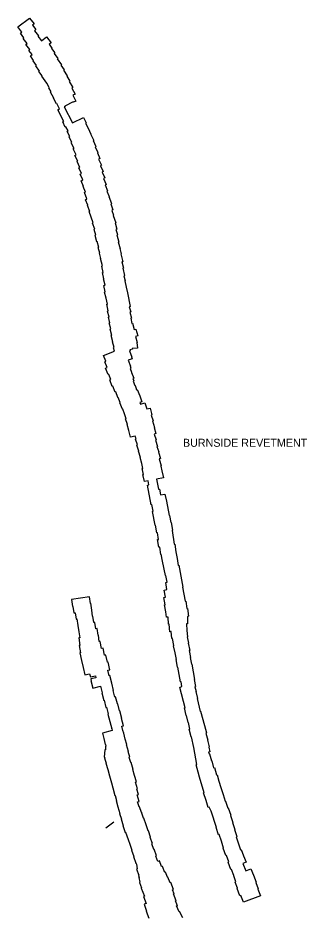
# Model space of a CAD drawing. Extents: x 2650582 to 3923188, y 277893 to 989177.
# Drawn here: x 3411893 to 3417673, y 574648 to 592623 of the extents above; entities that cross this region are included whole.
import ezdxf

# ---------------------------------------------------------------- set-up
doc = ezdxf.new("R2010")
doc.units = 0
doc.layers.add('Level 3', color=7, linetype='Continuous')

msp = doc.modelspace()

# ---------------------------------------------------------------- linework, layer by layer
at = {"layer": 'Level 3'}
msp.add_line((3413808, 576547), (3413650, 576422), dxfattribs=at)
for points in [[(3413582, 587665), (3413544, 587812), (3413550, 587813), (3413522, 587920), (3413528, 587921), (3413495, 588032), (3413508, 588035), (3413474, 588151), (3413471, 588150), (3413435, 588276), (3413448, 588280), (3413414, 588395), (3413427, 588399), (3413385, 588522), (3413399, 588527), (3413316, 588751), (3413329, 588756), (3413283, 588875), (3413289, 588878), (3413243, 588989), (3413271, 589008), (3413222, 589132), (3413242, 589140), (3413197, 589252), (3413205, 589255), (3413155, 589368), (3413192, 589384), (3413137, 589499), (3413161, 589511), (3413107, 589627), (3413127, 589637), (3413075, 589756), (3413087, 589761), (3413033, 589877), (3413054, 589887), (3413000, 590005), (3413014, 590011), (3412960, 590130), (3412972, 590136), (3412920, 590249), (3412929, 590253), (3412880, 590353), (3412894, 590365), (3412852, 590449), (3412840, 590443), (3412788, 590545), (3412807, 590555), (3412689, 590789), (3412724, 590808), (3412667, 590912), (3412664, 590910), (3412605, 591017), (3412611, 591021), (3412545, 591141), (3412559, 591150), (3412513, 591230), (3412520, 591235), (3412469, 591317), (3412372, 591461), (3412378, 591465), (3412313, 591555), (3412321, 591560), (3412248, 591666), (3412261, 591676), (3412194, 591768), (3412205, 591776), (3412142, 591866), (3412174, 591891), (3412110, 591976), (3412130, 591992), (3412053, 592095), (3412077, 592114), (3412000, 592215), (3412013, 592225), (3411943, 592317), (3411970, 592337), (3411893, 592445), (3412127, 592623)], [(3412127, 592623), (3412217, 592504), (3412185, 592478), (3412253, 592393), (3412222, 592368), (3412301, 592267), (3412292, 592261), (3412363, 592166), (3412463, 592246), (3412555, 592126), (3412518, 592097), (3412572, 592020), (3412564, 592014), (3412629, 591924), (3412616, 591914), (3412687, 591815), (3412675, 591806), (3412765, 591688), (3412751, 591677), (3412816, 591586), (3412803, 591577), (3412874, 591466), (3412868, 591462), (3412928, 591358), (3412919, 591353), (3412992, 591232), (3412970, 591218), (3413036, 591102), (3412989, 591077), (3413049, 590962), (3413005, 590938), (3413000, 590947), (3412828, 590860), (3412833, 590850), (3412820, 590844), (3412986, 590529), (3413203, 590636), (3413257, 590528), (3413245, 590522), (3413298, 590420), (3413294, 590418), (3413353, 590299), (3413350, 590297), (3413410, 590176), (3413399, 590171), (3413450, 590055), (3413437, 590049), (3413493, 589932), (3413481, 589926), (3413533, 589811), (3413506, 589798), (3413562, 589679), (3413542, 589669), (3413594, 589553), (3413574, 589543), (3413629, 589425), (3413605, 589413), (3413654, 589292), (3413634, 589284), (3413682, 589164), (3413673, 589161), (3413718, 589056), (3413708, 589051), (3413764, 588912), (3413747, 588906), (3413791, 588786), (3413768, 588776), (3413805, 588679), (3413798, 588676), (3413849, 588530), (3413834, 588525), (3413872, 588400), (3413852, 588393), (3413884, 588291), (3413869, 588286), (3413910, 588144), (3413900, 588141), (3413937, 588015), (3413933, 588013), (3413959, 587910), (3413951, 587908), (3413993, 587751), (3413971, 587746)], [(3413825, 585960), (3413804, 586030), (3413819, 586035), (3413785, 586146), (3413793, 586149), (3413758, 586273), (3413770, 586276), (3413736, 586402), (3413747, 586405), (3413720, 586525), (3413730, 586528), (3413704, 586640), (3413716, 586643), (3413684, 586762), (3413698, 586766), (3413670, 586898), (3413683, 586901), (3413655, 587023), (3413657, 587023), (3413626, 587144), (3413638, 587147), (3413607, 587276), (3413635, 587282), (3413605, 587408), (3413613, 587410), (3413583, 587534), (3413600, 587537), (3413568, 587662), (3413582, 587665)], [(3413971, 587746), (3414004, 587623), (3413987, 587619), (3414024, 587476), (3414010, 587471), (3414037, 587366), (3414030, 587365), (3414059, 587241), (3414055, 587240), (3414083, 587126), (3414086, 587127), (3414137, 586855), (3414117, 586851), (3414149, 586748), (3414128, 586742), (3414160, 586622), (3414150, 586620), (3414168, 586518), (3414185, 586522), (3414219, 586396), (3414250, 586404), (3414288, 586269), (3414242, 586256), (3414277, 586138), (3414272, 586136), (3414285, 586023), (3414177, 586014), (3414180, 586001), (3414129, 585989), (3414134, 585969), (3414125, 585967), (3414167, 585844), (3414164, 585843), (3414176, 585811), (3414098, 585781), (3414143, 585664), (3414136, 585662), (3414149, 585623), (3414134, 585617), (3414164, 585539), (3414162, 585538), (3414207, 585421), (3414193, 585416), (3414209, 585367), (3414198, 585363), (3414233, 585272), (3414234, 585272), (3414247, 585235), (3414264, 585191), (3414278, 585197), (3414328, 585066), (3414327, 585066), (3414372, 584949), (3414331, 584933), (3414342, 584899), (3414430, 584929), (3414473, 584808), (3414535, 584825), (3414573, 584688), (3414559, 584684), (3414594, 584571), (3414583, 584568), (3414626, 584436), (3414614, 584433), (3414653, 584316), (3414619, 584305)], [(3414143, 584239), (3414108, 584374), (3414111, 584375), (3414078, 584496), (3414081, 584497), (3414046, 584606), (3414055, 584609), (3414022, 584710), (3414026, 584711), (3413991, 584803), (3413984, 584800), (3413933, 584931), (3413938, 584932), (3413899, 585035), (3413893, 585033), (3413848, 585150), (3413838, 585145), (3413793, 585262), (3413778, 585256), (3413728, 585387), (3413748, 585395), (3413708, 585498), (3413696, 585493), (3413646, 585623), (3413674, 585634), (3413629, 585751), (3413649, 585759), (3413604, 585875), (3413825, 585960)], [(3414421, 583354), (3414393, 583494), (3414406, 583497), (3414379, 583615), (3414391, 583618), (3414367, 583716), (3414372, 583717), (3414335, 583835), (3414342, 583837), (3414301, 583961), (3414310, 583964), (3414270, 584081), (3414284, 584086), (3414244, 584202), (3414256, 584206), (3414237, 584264), (3414143, 584239)], [(3414619, 584305), (3414659, 584186), (3414642, 584180), (3414681, 584057), (3414673, 584054), (3414707, 583947), (3414700, 583945), (3414740, 583817), (3414719, 583811), (3414759, 583667), (3414751, 583664), (3414770, 583567), (3414773, 583568), (3414800, 583431), (3414662, 583403)], [(3415173, 579254), (3415156, 579351), (3415145, 579349), (3415119, 579499), (3415114, 579498), (3415090, 579642), (3415084, 579641), (3415057, 579796), (3415063, 579798), (3415039, 579929), (3415034, 579928), (3415005, 580073), (3415008, 580074), (3414982, 580215), (3414973, 580214), (3414956, 580354), (3414927, 580352), (3414915, 580500), (3414901, 580500), (3414898, 580642), (3414865, 580643), (3414852, 580752), (3414847, 580752), (3414822, 580889), (3414838, 580891), (3414812, 581039), (3414841, 581045), (3414815, 581186), (3414873, 581199), (3414848, 581337), (3414874, 581343), (3414849, 581476), (3414840, 581475), (3414786, 581761), (3414780, 581760), (3414756, 581900), (3414753, 581899), (3414729, 582045), (3414707, 582042), (3414682, 582193), (3414705, 582197), (3414682, 582329), (3414668, 582327), (3414642, 582484), (3414638, 582484), (3414584, 582759), (3414598, 582762), (3414571, 582893), (3414558, 582891), (3414482, 583282), (3414510, 583288), (3414495, 583369), (3414421, 583354)], [(3414662, 583403), (3414702, 583201), (3414720, 583204), (3414742, 583088), (3414831, 583104), (3414860, 582963), (3414862, 582963), (3414914, 582678), (3414922, 582679), (3414950, 582534), (3414957, 582534), (3414980, 582380), (3414974, 582379), (3415017, 582102), (3415028, 582103), (3415052, 581950), (3415051, 581949), (3415074, 581814), (3415075, 581814), (3415099, 581679), (3415111, 581681), (3415190, 581243), (3415181, 581241), (3415236, 580960), (3415247, 580962), (3415273, 580814), (3415283, 580815), (3415300, 580660), (3415285, 580659), (3415285, 580507), (3415264, 580507), (3415273, 580376), (3415269, 580376), (3415286, 580250), (3415278, 580249), (3415302, 580124), (3415299, 580124), (3415327, 579978), (3415319, 579977), (3415345, 579836), (3415339, 579835), (3415363, 579703), (3415367, 579704), (3415423, 579398), (3415416, 579397), (3415442, 579255), (3415437, 579255)], [(3413803, 579180), (3413767, 579321), (3413773, 579322), (3413733, 579474), (3413718, 579470), (3413688, 579584), (3413728, 579592), (3413696, 579745), (3413681, 579742), (3413652, 579885), (3413624, 579880), (3413596, 580022), (3413563, 580016), (3413535, 580159), (3413520, 580156), (3413501, 580286), (3413498, 580285), (3413479, 580414), (3413451, 580409), (3413431, 580538), (3413410, 580535), (3413391, 580664), (3413386, 580664), (3413368, 580781), (3413373, 580781), (3413353, 580920), (3413344, 580919), (3413325, 581048), (3412965, 580996), (3412985, 580856), (3412993, 580857), (3413012, 580730), (3413037, 580733), (3413057, 580605), (3413070, 580607), (3413089, 580478), (3413091, 580479), (3413111, 580352), (3413113, 580353), (3413131, 580232), (3413111, 580229), (3413133, 580079), (3413115, 580076), (3413144, 579932), (3413133, 579930), (3413163, 579777), (3413166, 579778), (3413195, 579634), (3413200, 579635), (3413229, 579492), (3413325, 579511), (3413341, 579447), (3413441, 579473), (3413451, 579433), (3413352, 579407), (3413359, 579378), (3413353, 579376), (3413391, 579224), (3413543, 579262), (3413576, 579133)], [(3413993, 578376), (3413971, 578465), (3414003, 578473), (3413966, 578616), (3413968, 578617), (3413929, 578768), (3413926, 578768), (3413890, 578910), (3413881, 578908), (3413845, 579050), (3413829, 579046), (3413794, 579178), (3413803, 579180)], [(3415410, 578035), (3415365, 578250), (3415357, 578248), (3415317, 578401), (3415332, 578405), (3415302, 578537), (3415297, 578535), (3415264, 578676), (3415257, 578674), (3415222, 578828), (3415234, 578831), (3415129, 579238), (3415135, 579240), (3415134, 579246), (3415173, 579254)], [(3415437, 579255), (3415433, 579253), (3415456, 579155), (3415450, 579154), (3415484, 579016), (3415476, 579014), (3415538, 578759), (3415545, 578761), (3415620, 578476), (3415625, 578477), (3415662, 578328), (3415652, 578325), (3415690, 578185), (3415682, 578182)], [(3413576, 579133), (3413572, 579132), (3413612, 578980), (3413617, 578981), (3413653, 578840), (3413665, 578843), (3413699, 578709), (3413689, 578706), (3413728, 578556), (3413731, 578556), (3413768, 578413), (3413769, 578414), (3413779, 578378)], [(3413779, 578378), (3413583, 578324), (3413613, 578216), (3413608, 578214), (3413640, 578096), (3413641, 578096), (3413651, 578062), (3413643, 578062), (3413645, 577988), (3413632, 577989), (3413620, 577847), (3413623, 577847), (3413628, 577825), (3413624, 577823)], [(3414095, 577956), (3414101, 577957), (3414061, 578092), (3414068, 578095), (3414037, 578204), (3414040, 578204), (3414008, 578323), (3414008, 578323), (3413993, 578376)], [(3415682, 578182), (3415713, 578048), (3415707, 578047), (3415731, 577952), (3415706, 577945), (3415716, 577908), (3415726, 577911), (3415764, 577770), (3415767, 577771), (3415803, 577633), (3415826, 577638), (3415866, 577489), (3415874, 577491), (3415909, 577366), (3415912, 577367), (3415949, 577235), (3415951, 577236), (3415994, 577097), (3415995, 577098), (3416038, 576965), (3416042, 576966), (3416090, 576827), (3416096, 576828), (3416148, 576683), (3416140, 576680), (3416190, 576540), (3416182, 576537), (3416228, 576400), (3416221, 576398), (3416270, 576257), (3416258, 576252), (3416306, 576113), (3416300, 576111), (3416341, 575994), (3416353, 575998), (3416401, 575868), (3416406, 575870), (3416454, 575745), (3416387, 575716), (3416447, 575572), (3416549, 575611), (3416601, 575483), (3416603, 575483), (3416656, 575344), (3416648, 575341), (3416697, 575209)], [(3414985, 575193), (3415006, 575201), (3414949, 575337), (3414938, 575333), (3414891, 575445), (3414885, 575442), (3414845, 575545), (3414828, 575538), (3414781, 575661), (3414766, 575655), (3414725, 575769), (3414689, 575756), (3414648, 575867), (3414660, 575872), (3414615, 576002), (3414612, 576001), (3414573, 576112), (3414583, 576115), (3414537, 576240), (3414546, 576244), (3414500, 576374), (3414498, 576373), (3414457, 576494), (3414454, 576493), (3414409, 576622), (3414406, 576621), (3414366, 576741), (3414360, 576739), (3414321, 576853), (3414317, 576852), (3414286, 576952), (3414314, 576960), (3414275, 577088), (3414304, 577096), (3414271, 577206), (3414282, 577209), (3414243, 577344), (3414263, 577350), (3414225, 577479), (3414223, 577479), (3414189, 577597), (3414196, 577599), (3414154, 577736), (3414150, 577735), (3414119, 577840), (3414130, 577844), (3414095, 577956)], [(3416697, 575209), (3416691, 575207), (3416741, 575071), (3416401, 574943), (3416348, 575080), (3416329, 575072), (3416275, 575219), (3416284, 575223), (3416239, 575345), (3416247, 575348), (3416208, 575474), (3416212, 575476), (3416162, 575601), (3416151, 575597), (3416094, 575745), (3416111, 575752), (3416065, 575881), (3416051, 575876), (3415999, 576023), (3416005, 576025), (3415960, 576166), (3415964, 576167), (3415919, 576296), (3415906, 576291), (3415856, 576437), (3415863, 576439), (3415753, 576764), (3415718, 576845), (3415699, 576840), (3415655, 576977), (3415653, 576977), (3415606, 577128), (3415617, 577131), (3415523, 577446), (3415497, 577545), (3415494, 577544), (3415457, 577693), (3415473, 577698), (3415410, 578035)], [(3413624, 577823), (3413656, 577722), (3413653, 577721), (3413690, 577596), (3413688, 577595), (3413726, 577472), (3413723, 577471), (3413764, 577330), (3413764, 577330), (3413793, 577232), (3413788, 577230), (3413832, 577079), (3413835, 577080), (3413865, 576979), (3413855, 576976), (3413893, 576852), (3413887, 576850), (3413928, 576720), (3413923, 576718), (3413961, 576605), (3413956, 576603), (3413998, 576480), (3413991, 576477), (3414039, 576340), (3414043, 576342), (3414094, 576195), (3414096, 576196), (3414130, 576102), (3414128, 576101), (3414168, 575987), (3414164, 575986), (3414208, 575859), (3414203, 575857), (3414249, 575727), (3414252, 575728), (3414260, 575707), (3414274, 575609), (3414266, 575606), (3414309, 575483), (3414301, 575480), (3414316, 575439), (3414313, 575439), (3414331, 575345), (3414321, 575341), (3414365, 575228), (3414358, 575225), (3414426, 575063)], [(3414426, 575063), (3414405, 575056), (3414456, 574918), (3414414, 574902), (3414465, 574765), (3414456, 574762), (3414509, 574623)], [(3415187, 574629), (3415126, 574757), (3415118, 574754), (3415065, 574868), (3415080, 574874), (3415044, 574969), (3415054, 574973), (3415004, 575110), (3415014, 575114), (3414985, 575193)]]:
    msp.add_lwpolyline(points, dxfattribs=at)

# ---------------------------------------------------------------- texts
msp.add_text('BURNSIDE REVETMENT', height=160, dxfattribs=at).set_placement((3415193, 584050))

doc.saveas('drawing.dxf')
